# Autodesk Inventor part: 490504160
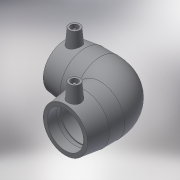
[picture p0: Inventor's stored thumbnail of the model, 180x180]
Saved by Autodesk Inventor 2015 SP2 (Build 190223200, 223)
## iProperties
Created: 2017-06
Part Number: 490504160
Material: Generic
Description: PLASSON 90° ELBOW 160
Document SubType Name: Modeling
Designer: KIM
Mass: 55.0731 g
Surface Area: 148.067 cm^2
Volume: 55.0731 cm^3
Density: 1 g/cm^3
Appearance: Default
Author: KIM
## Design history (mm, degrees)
derived "490504.ipt"
feature "Solid1::490504.ipt"
tag "TaggingFeature1"
body "Solid1"
other parameters: "d2" = 209, "d4" = 80.75, "d5" = 188.1, "d8" = 168 deg, "d10" = 34.8, "d11" = 11.6, "d14" = 17.6296, "d19" = 3.52592, "d20" = 168 deg, "d22" = 192.28, "d23" = 209, "d24" = 186.5116, "d29" = 106, "d30" = 15, "d31" = 113.05, "d34" = 5 deg, "d35" = 15, "d39" = 5 deg, "d41" = 4, "d42" = 14, "d43" = 0, "d45" = 4, "d46" = 14, "d47" = 0, "d50" = 136, "d51" = 34.8, "d52" = 87, "d54" = 90 deg, "d67" = 45 deg, "d71" = 90 deg, "d75" = 10.45, "d82" = 45 deg, "d83" = 87, "d84" = 188.1, "d86" = 94.05, "d87" = 90 deg, "d90" = 87, "d91" = 0, "d92" = 87, "d93" = 0, "d94" = 90 deg, "d95" = 96.14, "d98" = 323, "d101" = 3, "d102" = 0, "d103" = 3, "d104" = 0, "d105" = 25.23, "d106" = 6.3075, "d107" = 323, "d110" = 47.85, "L_" = 323, "L_1" = 87, "D_" = 209, "A_" = 106, "d_2" = 12
